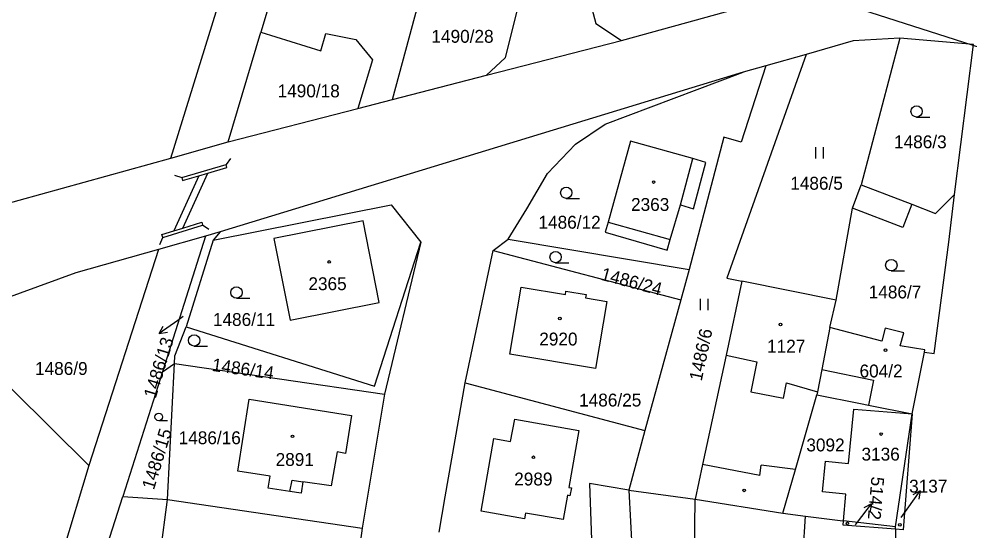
# Model space of a CAD drawing. Extents: x -779330 to -774454, y -1144748 to -1142831.
# Drawn here: x -777612.9 to -777487.4, y -1143917.3 to -1143849.7 of the extents above; entities that cross this region are included whole.
import ezdxf

# ---------------------------------------------------------------- set-up
doc = ezdxf.new("R2010")
doc.units = 0
for name, color, linetype in [('Hranice parcel', 7, 'Continuous'), ('Parcelní čísla', 7, 'Continuous'), ('Pop  PČ popisy', 7, 'Continuous'), ('Vnitřní kresba', 7, 'Continuous'), ('Vrstva 1', 7, 'Continuous'), ('Značky budov', 7, 'Continuous'), ('Značky kultur', 7, 'Continuous')]:
    doc.layers.add(name, color=color, linetype=linetype)

msp = doc.modelspace()

# ---------------------------------------------------------------- linework, layer by layer
at = {"layer": 'Hranice parcel'}
for p, q in [((-777592.84, -1143868.11), (-777573.74, -1143805.93)), ((-777533.28, -1143852.53), (-777506.15, -1143845.05)), ((-777585.29, -1143865.94), (-777580.95, -1143851.46)), ((-777551.16, -1143857.13), (-777533.28, -1143852.53)), ((-777496.53, -1143852.24), (-777501.62, -1143871.63)), ((-777486.78, -1143853.07), (-777496.53, -1143852.24)), ((-777489.3, -1143872.89), (-777486.78, -1143853.07)), ((-777508.91, -1143854.38), (-777514.23, -1143855.9)), ((-777514.23, -1143855.9), (-777517.23, -1143856.75)), ((-777517.23, -1143856.75), (-777586.35, -1143877.81)), ((-777563.57, -1143860.33), (-777551.16, -1143857.13)), ((-777535.48, -1143863.61), (-777517.23, -1143856.75)), ((-777585.29, -1143865.94), (-777568.15, -1143861.52)), ((-777568.15, -1143861.52), (-777563.57, -1143860.33)), ((-777592.84, -1143868.11), (-777585.29, -1143865.94)), ((-777628.63, -1143877.96), (-777592.84, -1143868.11)), ((-777586.35, -1143877.81), (-777588.26, -1143878.39)), ((-777586.35, -1143877.81), (-777587.25, -1143878.94)), ((-777588.26, -1143878.39), (-777594.5, -1143880.16)), ((-777588.26, -1143878.39), (-777593.96, -1143896.3)), ((-777587.25, -1143878.94), (-777590.82, -1143890.37)), ((-777550.27, -1143880.28), (-777548.26, -1143878.78)), ((-777548.26, -1143878.78), (-777524.36, -1143882.79)), ((-777594.5, -1143880.16), (-777603.71, -1143908.71)), ((-777559.82, -1143879.2), (-777564.64, -1143899.27)), ((-777553.97, -1143897.78), (-777550.27, -1143880.28)), ((-777550.27, -1143880.28), (-777525.46, -1143886.81)), ((-777524.36, -1143882.79), (-777525.46, -1143886.81)), ((-777504.92, -1143886.87), (-777517.38, -1143884.35)), ((-777525.46, -1143886.81), (-777530.2, -1143904.09)), ((-777505.77, -1143890.46), (-777504.92, -1143886.87)), ((-777494.89, -1143901.88), (-777493.26, -1143893.71)), ((-777593.96, -1143896.3), (-777592.37, -1143895.2)), ((-777593.28, -1143913.19), (-777592.37, -1143895.2)), ((-777592.37, -1143895.2), (-777564.64, -1143899.27)), ((-777593.96, -1143896.3), (-777599.22, -1143912.79)), ((-777553.97, -1143897.78), (-777530.2, -1143904.09)), ((-777564.64, -1143899.27), (-777567.58, -1143916.99)), ((-777502.61, -1143901.26), (-777494.89, -1143901.88)), ((-777497.09, -1143916.8), (-777494.89, -1143901.88)), ((-777530.2, -1143904.09), (-777532.35, -1143911.95)), ((-777603.71, -1143908.71), (-777609.79, -1143928.82)), ((-777604.4, -1143929.07), (-777599.22, -1143912.79)), ((-777599.22, -1143912.79), (-777593.28, -1143913.19)), ((-777532.35, -1143911.95), (-777523.56, -1143913.12)), ((-777503.95, -1143916), (-777503.65, -1143912.5)), ((-777595.58, -1143930.23), (-777593.28, -1143913.19)), ((-777593.28, -1143913.19), (-777567.58, -1143916.99)), ((-777523.95, -1143938.51), (-777523.56, -1143913.12)), ((-777523.56, -1143913.12), (-777511.98, -1143914.99)), ((-777497.09, -1143916.8), (-777503.95, -1143916)), ((-777497.09, -1143917.11), (-777497.09, -1143916.8)), ((-777567.58, -1143916.99), (-777569.92, -1143933.75))]:
    msp.add_line(p, q, dxfattribs=at)
for points in [[(-777530.89, -1143814.94), (-777537.99, -1143845.48), (-777536.71, -1143850.29), (-777533.28, -1143852.53)], [(-777574.4, -1143829.61), (-777575.32, -1143832.68), (-777580.95, -1143851.46)], [(-777563.57, -1143860.33), (-777558.4, -1143841.22), (-777546.16, -1143844.71)], [(-777546.16, -1143844.71), (-777548.69, -1143854.82), (-777551.16, -1143857.13)], [(-777580.95, -1143851.46), (-777573.03, -1143853.9), (-777572.39, -1143851.61), (-777568.41, -1143852.41), (-777566.21, -1143855.1), (-777568.15, -1143861.52)], [(-777496.53, -1143852.24), (-777502.67, -1143852.6), (-777508.91, -1143854.38)], [(-777508.91, -1143854.38), (-777519.36, -1143883.95), (-777517.38, -1143884.35)], [(-777514.23, -1143855.9), (-777517.49, -1143866), (-777519.79, -1143865.31), (-777524.36, -1143882.79)], [(-777548.26, -1143878.78), (-777545.82, -1143874.77), (-777543.08, -1143870.11), (-777539.4, -1143866.26), (-777535.48, -1143863.61)], [(-777523.87, -1143868.16), (-777532.09, -1143865.86), (-777535.08, -1143876.53), (-777535.46, -1143877.88), (-777527.27, -1143880.27), (-777526.85, -1143878.84), (-777525.52, -1143874.28), (-777523.79, -1143874.78), (-777522.14, -1143868.65), (-777523.87, -1143868.16)], [(-777504.92, -1143886.87), (-777502.79, -1143874.69), (-777501.62, -1143871.63)], [(-777501.62, -1143871.63), (-777494.94, -1143874.18), (-777491.79, -1143875.42), (-777489.3, -1143872.89)], [(-777493.26, -1143893.71), (-777491.96, -1143893.91), (-777490.04, -1143879.18), (-777489.3, -1143872.89)], [(-777587.25, -1143878.94), (-777563.75, -1143874.25), (-777559.82, -1143879.2)], [(-777565.32, -1143887.17), (-777567.45, -1143876.36), (-777579.26, -1143878.71), (-777577.09, -1143889.49), (-777565.32, -1143887.17)], [(-777594.5, -1143880.16), (-777605.41, -1143883.26), (-777622.97, -1143889.62)], [(-777590.82, -1143890.37), (-777565.93, -1143898.22), (-777559.82, -1143879.2)], [(-777546.57, -1143885.13), (-777540.72, -1143886.1), (-777540.64, -1143885.66), (-777537.99, -1143886.1), (-777538.06, -1143886.55), (-777535.25, -1143887.01), (-777536.75, -1143895.89), (-777548.06, -1143893.99), (-777546.57, -1143885.13)], [(-777517.38, -1143884.35), (-777519.48, -1143894.12), (-777522.58, -1143908.54), (-777523.56, -1143913.12)], [(-777622.97, -1143889.62), (-777613.76, -1143898.76), (-777603.71, -1143908.71)], [(-777592.37, -1143895.2), (-777592.32, -1143894.2), (-777590.82, -1143890.37)], [(-777505.77, -1143890.46), (-777506.83, -1143896.01), (-777507.39, -1143898.97), (-777507.47, -1143899.36)], [(-777493.26, -1143893.71), (-777493.2, -1143893.42), (-777496.45, -1143892.89), (-777496, -1143891.18), (-777498.45, -1143890.54), (-777498.9, -1143892.25), (-777505.77, -1143890.46)], [(-777557.4, -1143917.5), (-777556.59, -1143912.82), (-777553.97, -1143897.78)], [(-777570.89, -1143906.87), (-777571.66, -1143911.36), (-777575.4, -1143910.83), (-777575.64, -1143912.33), (-777577.12, -1143912.13), (-777579.98, -1143911.69), (-777579.73, -1143910.1), (-777583.99, -1143909.43), (-777582.5, -1143899.95), (-777568.97, -1143902.08), (-777569.78, -1143907.11), (-777570.89, -1143906.87)], [(-777511.98, -1143914.99), (-777510.32, -1143909.23), (-777507.47, -1143899.36)], [(-777507.47, -1143899.36), (-777501.73, -1143900.51), (-777500.66, -1143900.73), (-777494.89, -1143901.88)], [(-777503.65, -1143912.5), (-777506.75, -1143912.19), (-777506.35, -1143908.11), (-777503.28, -1143908.41), (-777502.61, -1143901.26)], [(-777538.92, -1143904.06), (-777540.24, -1143911.59), (-777539.93, -1143911.65), (-777540.11, -1143912.68), (-777540.43, -1143912.63), (-777540.99, -1143915.84), (-777545.98, -1143914.97), (-777546.11, -1143915.74), (-777551.86, -1143914.73), (-777550.19, -1143905.12), (-777547.96, -1143905.54), (-777547.4, -1143902.57), (-777538.92, -1143904.06)], [(-777494.89, -1143901.88), (-777496.09, -1143917.19), (-777497.09, -1143917.11)], [(-777532.35, -1143911.95), (-777537.52, -1143911.07), (-777537.18, -1143920.99)], [(-777511.98, -1143914.99), (-777508.97, -1143915.37), (-777504.07, -1143915.99), (-777503.95, -1143916)], [(-777497.09, -1143917.11), (-777504, -1143916.56), (-777503.95, -1143916)], [(-777497.09, -1143917.11), (-777496.98, -1143926.19), (-777492.18, -1143926.47), (-777492.28, -1143929.82), (-777492.21, -1143932.2), (-777492.29, -1143937.13)]]:
    msp.add_lwpolyline(points, dxfattribs=at)
at = {"layer": 'Pop  PČ popisy'}
for p, q in [((-777591.21, -1143889.02), (-777591.95, -1143889.54)), ((-777591.95, -1143889.54), (-777594.41, -1143891.26)), ((-777594.41, -1143891.26), (-777593.88, -1143890.28)), ((-777594.41, -1143891.26), (-777593.3, -1143891.1)), ((-777495.55, -1143914.48), (-777493.83, -1143912.02)), ((-777493.83, -1143912.02), (-777494.81, -1143912.55)), ((-777493.83, -1143912.02), (-777493.99, -1143913.13)), ((-777502.09, -1143916.17), (-777500.28, -1143913.77)), ((-777500.28, -1143913.77), (-777501.29, -1143914.27)), ((-777500.28, -1143913.77), (-777500.49, -1143914.87)), ((-777496.32, -1143915.58), (-777495.55, -1143914.48)), ((-777502.36, -1143916.53), (-777502.09, -1143916.17))]:
    msp.add_line(p, q, dxfattribs=at)
at = {"layer": 'Vnitřní kresba'}
for p, q in [((-777591.41, -1143870.65), (-777585.55, -1143868.95)), ((-777584.98, -1143868.13), (-777585.55, -1143868.95)), ((-777585.44, -1143869.34), (-777585.55, -1143868.95)), ((-777525.52, -1143874.28), (-777523.87, -1143868.16)), ((-777592.36, -1143870.34), (-777591.41, -1143870.65)), ((-777591.26, -1143877.33), (-777587.96, -1143870.07)), ((-777589.17, -1143870.42), (-777587.96, -1143870.07)), ((-777587.96, -1143870.07), (-777585.44, -1143869.34)), ((-777589.17, -1143870.42), (-777592.45, -1143877.71)), ((-777591.41, -1143870.65), (-777591.3, -1143871.04)), ((-777591.3, -1143871.04), (-777589.17, -1143870.42)), ((-777496.11, -1143877.24), (-777502.79, -1143874.69)), ((-777494.94, -1143874.18), (-777496.11, -1143877.24)), ((-777591.26, -1143877.33), (-777588.78, -1143876.56)), ((-777588.78, -1143876.56), (-777588.66, -1143876.94)), ((-777535.08, -1143876.53), (-777526.85, -1143878.84)), ((-777594.03, -1143878.2), (-777592.45, -1143877.71)), ((-777593.91, -1143878.58), (-777588.66, -1143876.94)), ((-777592.45, -1143877.71), (-777591.26, -1143877.33)), ((-777587.84, -1143877.51), (-777588.66, -1143876.94)), ((-777594.33, -1143879.49), (-777593.91, -1143878.58)), ((-777593.91, -1143878.58), (-777594.03, -1143878.2)), ((-777519.48, -1143894.12), (-777515.41, -1143895)), ((-777515.41, -1143895), (-777516.19, -1143898.97)), ((-777506.83, -1143896.01), (-777499.99, -1143897.4)), ((-777511.91, -1143899.82), (-777511.5, -1143897.79)), ((-777511.5, -1143897.79), (-777507.39, -1143898.97)), ((-777499.99, -1143897.4), (-777500.66, -1143900.73)), ((-777516.19, -1143898.97), (-777511.91, -1143899.82)), ((-777515.03, -1143910.03), (-777522.58, -1143908.54)), ((-777515.03, -1143910.03), (-777514.85, -1143908.64)), ((-777510.32, -1143909.23), (-777514.85, -1143908.64)), ((-777577.12, -1143912.13), (-777576.84, -1143910.62)), ((-777576.84, -1143910.62), (-777575.4, -1143910.83)), ((-777532.35, -1143911.95), (-777531.81, -1143921.92)), ((-777510.31, -1143935.05), (-777508.97, -1143915.37))]:
    msp.add_line(p, q, dxfattribs=at)
at = {"layer": 'Vrstva 1'}
msp.add_lwpolyline([(-776606.88, -1143822.95), (-777806.9, -1143438.86), (-777897.43, -1143721.71), (-776697.42, -1144105.81)], close=True, dxfattribs=at)
at = {"layer": 'Značky budov'}
for centre in [(-777529.05, -1143871.25), (-777571.93, -1143881.81), (-777541.44, -1143889.28), (-777512.28, -1143890.07), (-777498.42, -1143893.46), (-777576.79, -1143904.84), (-777499, -1143904.54), (-777544.95, -1143907.61), (-777517.09, -1143911.98), (-777503.45, -1143916.33), (-777496.51, -1143916.54)]:
    msp.add_circle(centre, 0.175, dxfattribs=at)
at = {"layer": 'Značky kultur'}
for p, q in [((-777494.3, -1143862.67), (-777492.55, -1143862.67)), ((-777507.62, -1143868.12), (-777507.62, -1143866.62)), ((-777506.62, -1143868.12), (-777506.62, -1143866.62)), ((-777540.6, -1143873.41), (-777538.85, -1143873.41)), ((-777542.01, -1143881.91), (-777540.26, -1143881.91)), ((-777497.64, -1143882.98), (-777495.89, -1143882.98)), ((-777584.19, -1143886.59), (-777582.44, -1143886.59)), ((-777522.84, -1143888.19), (-777522.84, -1143886.69)), ((-777521.84, -1143888.19), (-777521.84, -1143886.69)), ((-777589.78, -1143892.92), (-777588.03, -1143892.92)), ((-777594.45, -1143902.77), (-777593.28, -1143902.77))]:
    msp.add_line(p, q, dxfattribs=at)
for centre, radius in [((-777494.3, -1143861.92), 0.75), ((-777540.6, -1143872.66), 0.75), ((-777542.01, -1143881.16), 0.75), ((-777497.64, -1143882.23), 0.75), ((-777584.19, -1143885.84), 0.75), ((-777589.78, -1143892.17), 0.75), ((-777594.46, -1143902.27), 0.502)]:
    msp.add_circle(centre, radius, dxfattribs=at)

# ---------------------------------------------------------------- texts
at = {"layer": 'Parcelní čísla'}
for s, p in [('1490/28', (-777558.42, -1143852.85)), ('1490/18', (-777578.75, -1143860.06)), ('1486/3', (-777497.28, -1143866.79)), ('1486/5', (-777511, -1143872.26)), ('2363', (-777532.04, -1143875.06)), ('1486/12', (-777544.27, -1143877.41)), ('2365', (-777574.68, -1143885.53)), ('1486/7', (-777500.63, -1143886.62)), ('1486/11', (-777587.3, -1143890.26)), ('2920', (-777544.17, -1143892.84)), ('1127', (-777514.06, -1143893.78)), ('1486/9', (-777610.81, -1143896.73)), ('604/2', (-777501.84, -1143897.06)), ('1486/25', (-777538.9, -1143900.9)), ('1486/16', (-777591.83, -1143905.88)), ('3092', (-777508.87, -1143906.83)), ('3136', (-777501.58, -1143908.04)), ('2891', (-777579.01, -1143908.75)), ('2989', (-777547.48, -1143911.33)), ('3137', (-777495.29, -1143912.27))]:
    msp.add_text(s, height=1.7, dxfattribs=at).set_placement(p)
for s, rotation, p in [('1486/24', 345, (-777536.15, -1143884.14)), ('1486/6', 78, (-777522.71, -1143897.62)), ('1486/13', 73, (-777594.87, -1143899.94)), ('1486/14', 352, (-777587.5, -1143896.19)), ('1486/15', 73, (-777595.1, -1143911.99)), ('514/2', 265, (-777500.26, -1143910.11))]:
    msp.add_text(s, height=1.7, rotation=rotation, dxfattribs=at).set_placement(p)

doc.saveas('drawing.dxf')
